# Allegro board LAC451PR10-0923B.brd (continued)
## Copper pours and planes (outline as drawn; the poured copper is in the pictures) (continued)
GND on IN4 (solid shape): 77.3,141.85 77.47,141.77 77.55,141.6 77.55,138.35 77.77,137.82 78.3,137.6 81.2,137.6 81.73,137.82 81.95,138.35 81.95,141.6 82.03,141.77 82.2,141.85 82.3,141.85 82.47,141.77 82.55,141.6 82.55,141.25 82.77,140.72 83.3,140.5 83.8,140.5 83.97,140.42 84.05,140.25 84.05,131.8 84.05,131.7 84.07,131.61 84.07,130.49 83.73,130.15 75.79,130.15 75.45,130.48 75.45,140.25 75.53,140.42 75.7,140.5 76.2,140.5 76.73,140.72 76.95,141.25 76.95,141.6 77.03,141.77 77.2,141.85
GND on IN4 (solid shape): 284.65,140.78 285.18,140.56 285.4,140.03 285.4,137.76 285.57,137.71 285.95,137.44 286.1,137 286.1,133.65 286.46,132.76 287.35,132.4 295.94,132.4 296.56,132.4 296.66,132.38 296.74,132.32 298.75,131.45 300.76,132.32 300.84,132.38 300.94,132.4 303.5,132.4 304.66,131.96 305.23,130.86 305.24,130.75 305.25,130.65 305.25,111.25 305.17,111.08 304.47,110.78 304.25,110.25 304.25,108.65 304.47,108.12 305.17,107.82 305.25,107.65 305.25,107.25 305.17,107.08 305,107 303.37,107 302.84,106.78 302.62,106.25 302.62,105.25 302.54,105.08 302.37,105 290.94,105 290.81,105.13 290.81,106.16 291.27,106.61 302.06,106.61 302.22,106.78 302.69,107.31 303.37,107.51 304.45,107.51 303.93,107.98 303.74,108.65 303.74,110.25 304.02,111.04 304.74,111.48 304.74,130.65 304.73,130.75 304.72,130.86 304.3,131.6 303.5,131.89 301.05,131.89 298.75,130.94 296.45,131.89 295.94,131.89 287.35,131.89 287.28,131.89 287.22,131.89 285.02,131.89 284,132.9 284,140.53 284.08,140.7 284.25,140.78
GND on IN4 (solid shape): outline of 122 points within 0.25,27.1 71.76,141.85
GND on IN4 (solid shape): outline of 706 points within 167.46,44.09 183.27,47.33
GND on IN4 (solid shape): outline of 158 points within 98.45,126.72 266.9,142.2
GND on IN4 (solid shape): outline of 196 points within 26.95,0.25 304.55,42.16
GND on IN4 (solid shape): outline of 1881 points within 94.37,39.68 115.32,51.68
GND on GND1: outline of 482 points within 0.26,0.26 305.25,142.19
GND on GND2: outline of 482 points within 0.26,0.26 305.25,142.19
GND on VCC: outline of 114 points within 281.91,54.17 305.25,140.77
GND on VCC: outline of 82 points within 201.57,129.07 266.9,142.19
GND on VCC: 1,27.11 0.47,27.32 0.26,27.85 0.26,60.3 0.47,60.83 1,61.05 9.19,61.05 9.12,60.97 9.12,60.76 10.39,59.49 10.39,55.17 11.93,53.63 38.47,53.63 38.83,53.27 38.83,48.27 38.35,47.79 17.9,47.79 16.36,46.24 16.36,40.7 19.93,37.12 28.54,37.12 28.47,36.94 28.44,36.75 28.44,27.35 28.37,27.18 28.2,27.11 27.2,27.11 27.03,27.18 26.95,27.35 26.95,30.65 27.02,30.68 27.12,30.74 27.2,30.82 27.27,30.92 27.31,31.02 27.34,31.13 27.36,31.25 27.35,31.36 27.32,31.47 27.27,31.58 27.2,31.67 27.12,31.75 27.03,31.82 26.92,31.87 26.81,31.9 26.7,31.91 26.58,31.89 26.47,31.86 26.37,31.82 26.27,31.75 26.19,31.67 26.13,31.57 26.1,31.51 6.3,31.51 6.27,31.57 6.21,31.67 6.13,31.75 6.03,31.82 5.93,31.86 5.82,31.89 5.7,31.91 5.59,31.9 5.48,31.87 5.37,31.82 5.28,31.75 5.2,31.67 5.13,31.58 5.08,31.47 5.05,31.36 5.04,31.25 5.06,31.13 5.09,31.02 5.13,30.92 5.2,30.82 5.28,30.74 5.38,30.68 5.44,30.65 5.44,27.35 5.37,27.18 5.2,27.11
GND on VCC: 163.04,82.61 166.99,78.66 172.64,78.66 173.22,78.08 178.3,78.08 178.75,77.63 179.76,77.63 180.08,77.32 185.94,77.32 186.83,78.21 190.77,78.21 191.34,78.78 193.54,78.78 194.18,78.14 200.66,78.14 200.82,77.98 200.82,76.06 202.18,74.71 205.1,74.71 229.21,50.6 229.21,39 227.94,37.73 227.94,37.52 227.95,37.51 166.27,37.51 166.12,37.56 165.56,38.48 164.7,38.79 164,38.79 163.14,38.48 162.59,37.56 162.43,37.51 159.8,37.51 159.63,37.58 159.56,37.75 159.56,39.2 157.1,41.65 154.65,39.2 154.65,37.75 154.57,37.58 154.4,37.51 152.4,37.51 152.23,37.58 152.16,37.75 152.16,38.75 151.93,39.28 151.4,39.51 142.4,39.51 141.87,39.28 141.65,38.75 141.65,37.75 141.57,37.58 141.4,37.51 84.03,37.51 84.05,37.52 84.05,37.73 82.78,39 82.78,58.22 100.53,75.98 109.3,75.98 123.52,90.2 148.33,90.2 148.94,89.59 148.94,86.92 150.11,85.76 155.27,85.76 156.18,86.67 156.18,87.92 162.17,87.92 163.04,87.05
GND on VCC: 73.12,72.68 73.12,77.65 75.39,79.92 76.7,79.92 76.93,79.68 76.93,75.83 73.78,72.68
GND on VCC: 53.16,54.14 52.68,54.62 52.68,56.57 52.91,56.8 55.24,56.8 55.47,56.57 55.47,54.37 55.24,54.14
GND on VCC: 58.63,127.67 56.86,129.44 56.45,129.71 55.97,129.8 55.47,129.8 55.47,129.81 51.25,129.81 50.02,130.32 49.51,131.55 49.51,139.65 49.72,140.18 50.25,140.39 51.85,140.39 52.38,140.62 52.6,141.15 52.6,141.6 52.68,141.77 52.85,141.85 59.3,141.85 59.47,141.77 59.54,141.6 59.54,141.25 59.77,140.72 60.3,140.5 60.8,140.5 60.97,140.42 61.05,140.25 61.05,131.8 61.67,131.06 62.51,131.55 73.99,131.55 74.83,131.06 75.46,131.8 75.46,140.25 75.53,140.42 75.7,140.5 76.2,140.5 76.73,140.72 76.96,141.25 76.96,141.6 77.03,141.77 77.2,141.85 77.3,141.85 77.47,141.77 77.55,141.6 77.55,138.35 77.77,137.82 78.3,137.6 81.2,137.6 81.73,137.82 81.96,138.35 81.96,141.6 82.03,141.77 82.2,141.85 82.3,141.85 82.47,141.77 82.54,141.6 82.54,141.25 82.77,140.72 83.3,140.5 83.8,140.5 83.97,140.42 84.04,140.25 84.04,138.35 84.05,131.8 84.67,131.06 85.51,131.55 96.99,131.55 97.83,131.06 98.46,131.8 98.46,140.25 98.53,140.42 98.7,140.5 100.85,140.5 101.38,140.28 101.59,139.75 101.59,134.35 102.85,130.3 106.19,127.67
GND on GND3: outline of 483 points within 0.26,0.26 305.25,142.19
GNDA on TOP (solid shape): 292.81,77.44 292.81,75.43 292.54,75.16 291.65,75.16 291.5,75.31 291.5,76.52 291.68,76.69 291.68,77.42 291.88,77.62 292.63,77.62
GNDA on TOP (solid shape): 300.06,76.75 300.06,74.46 299.84,74.25 298.92,74.25 298.34,74.82 298.34,75.39 298.07,75.66 296.56,75.66 296.08,75.19 294.49,75.19 294.43,75.26 294.43,76.6 294.8,76.98 299.83,76.98
GNDA on TOP (solid shape): 294.06,74.06 294.06,73.79 293.78,73.5 293.02,73.5 292.15,72.64 291.23,72.64 291.16,72.71 291.16,73.48 291.19,73.51 292.05,73.51 292.77,74.22 293.07,74.22 293.16,74.32 293.81,74.32
GNDA on TOP (solid shape): 295.1,67.13 295.1,66.58 295.35,66.34 295.79,66.34 295.79,66.34 296.34,66.34 296.7,65.98 296.7,65.54 296.52,65.36 296.15,65.36 295.95,65.56 295.39,65.56 295.32,65.49 294.51,65.49 294.17,65.83 294.17,66.36 294,66.52 294,67.13 294.16,67.28 294.95,67.28
GNDA on GND1, GND2, GND3: 285.45,40.17 281.91,43.7 281.91,56.95 282.27,57.31 288.24,57.31 289.15,58.22 289.15,67.24 289.26,67.34 291.29,67.34 291.69,67.75 291.69,72.28 291.29,72.68 290.53,72.68 290.29,72.91 290.29,78.41 290.53,78.65 293.87,78.65 295.52,77 300.35,77 300.71,76.64 300.71,62.12 297.81,59.22 294.89,59.22 292.96,57.29 292.96,54.92 293.11,54.77 293.29,54.77 294.14,53.92 303.89,53.92 303.89,52.17 303.82,52 303.65,51.92 292.15,51.92 291.41,51.3 291.9,50.46 291.9,45.08 291.41,44.24 292.15,43.62 303.65,43.62 303.82,43.54 303.89,43.37 303.89,41.31 297.43,41.31 296.28,40.17
GNDA on VCC: 285.45,40.17 281.91,43.7 281.91,56.95 282.27,57.31 288.24,57.31 289.15,58.22 289.15,67.24 289.26,67.34 291.29,67.34 291.69,67.75 291.69,72.28 291.29,72.68 290.53,72.68 290.29,72.91 290.29,78.41 290.53,78.65 293.87,78.65 295.52,77 300.35,77 300.71,76.64 300.71,62.12 297.81,59.22 294.89,59.22 292.96,57.29 292.96,54.92 293.11,54.77 293.29,54.77 294.14,53.92 302.88,53.92 302.88,52.94 292.15,52.94 290.52,51.86 290.88,49.94 290.88,45.6 290.52,43.68 292.15,42.6 302.88,42.6 302.88,41.31 297.43,41.31 296.28,40.17
VCCSA_B+ on TOP (solid shape): 130.21,112.37 130.21,110.97 128.94,110.97 128.75,111.16 128.75,112.18 129,112.43 130.15,112.43
VCCSA_B+ on BOTTOM (solid shape): 130.91,112.87 130.4,112.87 130.21,112.68 130.21,110.13 130.16,110.08 127.8,110.08 127.73,110.14 127.73,110.4 128.31,110.4 128.31,110.91 127.73,110.91 127.73,112.81 128.37,113.45 130.91,113.45
VDD_1.2V on BOTTOM (solid shape): 81.38,76.42 81.38,74.9 81.32,74.84 79.22,74.84 79.16,74.9 79.16,75.2 79.23,75.38 79.2,75.58 79.22,75.6 79.6,75.6 79.92,75.92 79.92,76.49 79.98,76.55 81.25,76.55
VIN_1.8VALW on TOP (solid shape): 295.81,5.43 295.81,4.9 295.29,4.9 295.27,4.89 295.27,4.35 295.82,4.35 295.82,4.1 295.29,4.1 295.27,4.09 295.27,3.55 295.82,3.55 295.82,3.07 295.62,2.87 294.74,2.87 293.77,3.83 291.67,3.83 290.85,4.64 290.85,4.94 291.02,5.1 291.7,5.1 292.21,5.61 295.63,5.61
VIN_1V_PRIM on TOP (solid shape): 245.91,94.27 245.91,90.46 246,90.37 246,89.28 246.56,89.28 246.56,89.1 246,89.1 246,88.68 245.76,88.44 245.09,88.44 244.64,88.9 244.64,90.71 243.93,91.42 242.88,91.42 242.8,91.51 242.8,92.74 244.64,94.59 245.59,94.59
VIN_1VS_VCCIO on TOP (solid shape): 239.91,42.61 239.91,41.86 239.8,41.75 239.29,41.75 238.89,41.35 237.17,41.35 236.96,41.56 236.96,42.69 237.27,43 237.27,43.91 237.37,44.01 238.5,44.01
VIN_1VS_VCCIO on BOTTOM (solid shape): 239.19,44.22 239.83,44.22 240.08,43.96 240.08,41.88 239.91,41.71 239.02,41.71 238.69,41.38 237.24,41.38 237.11,41.51 237.11,43.95 237.38,44.21 239.01,44.21 239.01,44.74 239.19,44.74
+BL_PWR_SRC on TOP (solid shape): outline of 86 points within 89.76,110.68 94.46,114.84
+BL_PWR_SRC on BOTTOM (solid shape): 95.34,111.97 95.65,111.62 96.04,111.88 96.07,111.88 96.09,111.87 96.2,111.82 96.32,111.82 96.34,111.83 97.15,111.27 97.41,111.1 97.44,111.02 97.46,110.98 96.8,110.05 96.71,110.05 96.49,110.21 95.78,110.71 94.96,110.71 94.87,110.8 93.08,110.8 92.95,110.93 92.95,111.18 93.53,112.01 95.32,112.01
+DC_IN on TOP (solid shape): 78.08,101.52 78.08,100.87 78.28,100.67 78.28,99.65 78.15,99.52 76.89,99.52 76.29,98.92 76.29,98.57 75.79,98.08 74.14,98.08 73.84,97.78 73.75,97.75 73.67,97.81 73.18,97.97 73.15,97.45 73.18,97.37 73.15,97.29 73.04,97.15 73.01,96.98 73,96.94 72.11,96.05 70.58,96.05 70.39,96.24 70.39,99.73 70.65,99.98 76.43,99.98 77.26,100.82 77.26,101.47 77.41,101.62 77.98,101.62
+DC_IN_SS on TOP (solid shape): 70.08,81.31 70.08,79.28 69.82,79.03 67.41,79.03 67.16,79.28 67.16,81.14 67.18,81.21 67.54,81.57 69.82,81.57
+DC_IN_SS on TOP (solid shape): 75.92,92.74 75.92,90.46 75.54,90.08 73.63,90.08 72.87,90.84 71.47,90.84 70.71,91.6 69.31,91.6 69.19,91.73 69.19,95.03 69.7,95.54 73.12,95.54
+DC_IN_SS on BOTTOM (solid shape): 8.81,59.91 8.91,59.85 8.88,59.74 9.12,59.11 9.35,59.74 9.32,59.85 9.42,59.91 14.41,59.91 14.74,59.58 14.74,57.25 13.22,55.72 8.48,55.72 7.66,56.55 7.66,57.03 7.66,57.04 7.69,57.18 7.66,57.33 7.66,57.34 7.66,59.47 8.1,59.91
+DC_IN_SS on VCC: 12.14,54.14 10.89,55.38 10.89,59.49 11.43,60.03 16.27,60.03 16.27,61.03 44.99,61.03 59.14,68.87 67.65,82.63 69.25,82.63 72.27,85.65 69.25,88.67 68.89,88.67 69.07,91.72 68.95,94.78 74.54,94.78 75.03,94.29 75.03,80.28 72.62,77.86 72.62,72.53 57.4,57.31 52.7,57.31 52.17,56.78 52.17,54.62 51.68,54.14
+DCIN on TOP (solid shape): 56.61,53.56 58.39,53.56 58.39,50.07 58.27,49.95 57.44,49.95 57.25,50.14 57.25,52.17 56.49,52.93 55.26,52.93 55.15,53.03 55.15,53.82 55.22,53.88 56.3,53.88
+DCIN_JACK on TOP (solid shape): 77.06,103.79 77.06,101 76.43,100.36 72.87,100.36 72.24,101 72.24,103.79 72.62,104.17 76.68,104.17
+DCIN_JACK on BOTTOM (solid shape): 75.79,104.56 76.55,102.14 76.81,101.25 76.68,100.87 73.76,100.24 73.38,100.49 72.62,103.03 72.49,103.41 72.62,103.92 75.41,104.68
+DCPRTC on BOTTOM (solid shape): 168.8,80.93 168.8,80.55 169.41,79.94 169.41,79.59 169.23,79.41 169.08,79.41 168.9,79.59 168.9,79.69 168.85,79.99 168.57,80.12 168.38,80.31 168.38,80.72 168.38,80.74 168.38,81.01 168.46,81.08 168.65,81.08
+DOCK_PWR_BAR on TOP (solid shape): 10.89,46.07 14.45,46.07 14.58,45.94 14.58,43.98 14.26,43.66 8.1,43.66 7.72,44.04 7.72,46.64 7.97,46.9 10.07,46.9
+DOCK_PWR_BAR on TOP (solid shape): outline of 217 points within 130.58,128.2 135.35,136.9
+DOCK_PWR_BAR on BOTTOM (solid shape): 173.64,136.44 173.64,129.6 174.89,128.35 174.89,126.22 174.74,126.07 172.08,126.07 171.93,126.22 171.93,136.36 172.21,136.64 173.44,136.64
+DOCK_PWR_BAR on BOTTOM (solid shape): 15.59,46.4 15.59,44.17 15.31,43.9 13.26,43.9 12.84,43.48 12.84,42.58 12.63,42.38 10.5,42.38 10.3,42.58 10.3,43.33 10.22,43.4 7.66,43.4 7.38,43.68 7.38,46.39 7.67,46.69 15.3,46.69
+DOCK_PWR_BAR on IN2 (solid shape): outline of 2764 points within 75.16,121.51 133.74,140.58
+DOCK_PWR_BAR on IN3 (solid shape): outline of 10657 points within 6.32,43.72 136.88,140.58
+DOCK_PWR_BAR on VCC: 131.01,128.69 130.66,129.04 130.66,129.98 131.93,131.25 131.93,136.2 132.28,136.56 133.47,136.56 134.11,135.92 171.65,135.92 172.29,136.56 173.48,136.56 173.58,136.45 173.58,131.99 172.95,131.35 160.37,131.35 159.36,130.34 139.95,130.34 138.3,128.69
+EDP_VDD on TOP (solid shape): 88.64,109.62 88.64,108.83 89.2,108.83 89.2,108.66 88.64,108.66 88.64,107.95 88.49,107.79 86.9,107.79 86.64,108.06 86.64,109.72 86.78,109.86 88.4,109.86
+LCDVDD on TOP (solid shape): 92.75,109.38 92.75,107.6 92.54,107.4 91.25,107.4 91.11,107.26 90.64,107.26 90.48,107.41 89.06,107.41 88.81,107.67 88.81,108.49 89.38,108.49 89.38,109 88.81,109 88.81,109.44 88.94,109.57 92.56,109.57
+LCDVDD on BOTTOM (solid shape): 92.75,108.24 92.75,106.46 93.44,105.95 93.7,105.76 93.7,105.63 93.38,105.19 93.25,105.13 92.3,105.83 92.11,105.95 92.11,106.24 92.19,106.59 91.97,106.87 91.96,106.88 91.6,107.73 91.6,108.37 91.92,108.49 92.49,108.49
+PBATT on TOP (solid shape): 76.17,55.66 76.17,49.47 76.01,49.31 75.67,49.31 75.66,49.31 73.38,49.31 73,49.69 73,55.15 73.63,55.79 76.05,55.79
+PBATT on BOTTOM (solid shape): 23.59,48.04 23.59,44.87 25.12,43.34 25.12,39.4 24.74,39.02 22.07,39.02 21.94,39.15 21.94,41.37 20.58,42.73 17.09,42.73 16.74,43.09 16.74,45.63 17.12,46.01 18.9,46.01 21.05,48.17 23.47,48.17
+PBATT on VCC: 20.14,37.63 16.86,40.91 16.86,46.03 18.11,47.28 38.98,47.28 43.05,43.21 46.69,43.21 49.1,45.63 59.01,45.63 64.97,51.6 75.56,51.6 76.17,50.98 76.17,44.84 74.01,42.68 74.01,39 73.53,38.52 59.87,38.52 57.7,39.8 55.53,38.52 37.42,38.52 37.42,39.75 34.75,42.42 32.08,39.75 32.08,38.52 29.2,38.52 28.31,38.28 27.66,37.63
+PWR_SRC on TOP (solid shape): 89.33,112.48 89.33,110.86 89.13,110.65 86.84,110.65 86.46,111.03 86.46,112.68 86.59,112.81 89,112.81
+PWR_SRC on TOP (solid shape): 98.45,120.38 98.45,116.43 97.38,115.36 94.99,115.36 94.09,116.26 94.09,120.47 95.1,121.47 97.36,121.47
+PWR_SRC on TOP (solid shape): 204.18,105.06 204.18,101.27 202.84,99.93 200.64,99.93 200.02,100.55 200.02,105.02 200.63,105.62 203.62,105.62
+PWR_SRC on TOP (solid shape): 226.1,79.16 226.65,79.16 226.65,79.71 226.9,79.71 226.9,79.18 226.91,79.18 226.91,79.16 227.56,79.16 227.68,79.03 227.68,78.01 227.49,77.82 225.21,77.82 225.08,77.95 225.08,79.03 225.21,79.16 225.85,79.16 225.85,79.71 226.1,79.71
+PWR_SRC on TOP (solid shape): 47.47,46.26 47.47,41.94 45.95,40.42 40.29,40.42 40.23,40.48 40.23,41.18 40.29,41.25 41.31,41.25 41.56,41.5 41.56,44.04 41.16,44.45 40.14,44.45 39.7,44.89 39.7,46.36 39.84,46.5 41.49,46.5 41.76,46.77 46.96,46.77
+PWR_SRC on TOP (solid shape): 67.59,64.38 67.59,63.55 68.12,63.55 68.12,63.3 67.59,63.3 67.59,62.75 68.12,62.75 68.12,62.55 68.06,62.5 67.59,62.5 67.59,62.03 67.38,61.82 66.11,61.82 65.83,62.1 65.84,62.13 65.84,62.32 65.77,62.49 65.76,62.5 65.76,62.55 65.77,62.56 65.85,62.82 65.76,63.08 65.76,64.47 66,64.72 67.26,64.72
+PWR_SRC on BOTTOM (solid shape): 232.53,93.15 232.53,91.66 231.15,90.28 229.46,90.28 228.06,91.68 228.06,94.78 228.32,95.03 230.65,95.03
+PWR_SRC on BOTTOM (solid shape): 96.7,100.16 96.7,99.2 96.68,99.18 96.14,99.18 96.14,98.45 96.16,98.42 96.68,98.42 96.68,97.98 96.15,97.98 96.14,97.96 96.14,97.23 96.68,97.23 96.68,96.3 96.37,95.98 93.18,95.98 92.54,96.62 92.54,99.73 93.44,100.63 96.23,100.63
+PWR_SRC on BOTTOM (solid shape): 54.26,134.56 54.59,134.54 54.61,134.54 54.67,134.48 54.67,134.17 54.66,134.07 54.67,133.97 54.67,131.77 54.54,131.64 53.22,131.64 53.04,131.83 53.04,133.37 53.08,133.45 53.43,133.51 53.56,133.76 53.56,134.34 53.55,134.41 53.53,134.47 53.53,134.57 53.62,134.62 53.94,134.62
+PWR_SRC on BOTTOM (solid shape): 47.34,48.17 47.34,41.31 46.45,40.42 40.29,40.42 40.23,40.48 40.23,41.18 40.29,41.25 41.18,41.25 41.56,41.63 41.56,42.83 41.18,43.21 40.91,43.21 40.83,43.25 40.81,43.34 40.49,43.74 40.16,43.34 40.14,43.25 40.06,43.21 38.83,43.21 37.4,44.65 37.4,45.87 38.79,45.87 39.14,46.22 38.79,46.58 37.4,46.58 37.4,47.11 37.95,47.66 41.83,47.66 42.21,47.53 42.47,47.84 42.47,47.86 42.49,47.88 42.49,48.45 42.73,48.7 46.81,48.7
+PWR_SRC on BOTTOM (solid shape): outline of 352 points within 209.5,75.99 234.19,80.81
+PWR_SRC on IN1 (solid shape): 62.02,128 62.78,128 63.55,127.23 63.55,127.2 64.26,126.49 64.26,123.29 63.85,122.89 61.74,122.89 61.28,123.35 61.28,126.04 60.99,126.33 60.98,126.34 60.76,126.87 60.41,127.33 57.58,130.16 57.1,130.52 56.26,130.8 55.97,130.82 53.26,130.82 53.06,131.02 53.06,133.26 53.33,133.53 56.5,133.53
+PWR_SRC on IN2 (solid shape): 64.23,125.81 64.23,123.56 63.94,123.28 62.29,123.28 62.17,123.4 62.17,125.87 62.37,126.08 63.96,126.08
+PWR_SRC on IN2 (solid shape): 87.97,112.9 87.97,111 87.64,110.67 86.78,110.67 86.47,110.98 86.47,111.54 86.25,111.77 85.42,111.77 84.76,112.43 84.76,112.87 85.99,114.1 86.76,114.1
+PWR_SRC on IN3 (solid shape): outline of 115 points within 200.6,93.41 230.96,104.59
+PWR_SRC on VCC: 43.26,43.72 39.34,47.64 39.34,53.27 39.7,53.63 55.45,53.63 55.98,54.16 55.98,56.57 56.21,56.8 57.61,56.8 72.98,72.17 73.99,72.17 77.44,75.62 77.44,79.9 76.91,80.43 76.02,80.43 75.54,80.91 75.54,102.93 89.1,116.49 96.89,116.49 97.13,116.26 97.13,115.58 88.11,106.57 88.11,101.91 89.78,100.24 93.34,100.24 93.7,99.88 93.7,96.79 92.83,95.92 84.45,95.92 82.52,93.99 82.52,69.86 58.79,46.14 48.89,46.14 46.48,43.72
+PWR_SRC_AC on TOP (solid shape): 14.64,51.6 14.64,47.02 14.45,46.83 11.08,46.83 10.51,47.41 7.97,47.41 7.59,47.79 7.59,50.07 8.23,50.71 9.89,50.71 10.83,50.71 11.12,51 11.12,51.72 11.19,51.79 14.45,51.79
+PWR_SRC_AC on BOTTOM (solid shape): 10.77,50.52 10.77,49.06 11.15,48.68 12.23,48.68 12.61,49.06 12.61,50.39 12.76,50.54 13.65,50.54 13.65,49.17 14.01,48.81 14.36,49.17 14.36,50.54 14.94,50.54 15.05,50.43 15.05,47.57 14.7,47.21 7.97,47.21 7.02,48.17 5.56,48.17 5.37,48.36 5.37,49.18 6.93,50.74 10.54,50.74
+PWR_SRC_AC on BOTTOM (solid shape): 65.25,56.1 65.25,55.6 63.73,53.44 63.24,53.25 62.46,53.77 61.81,54.22 61.8,54.23 61.48,53.78 61.12,54.04 61.43,54.48 60.83,54.91 60.82,54.91 60.61,54.62 60.5,54.47 60.14,54.73 60.45,55.18 60.3,55.28 59.82,55.61 59.81,55.68 59.78,55.87 59.98,56.17 60.46,56.84 60.5,56.81 60.97,56.91 60.91,57.39 60.87,57.42 61.57,58.39 61.95,58.39
+PWR_SRC_AC on IN2 (solid shape): outline of 2557 points within 7.47,47.02 65.12,56.42
+PWR_SRC_R on BOTTOM (solid shape): 284.78,10.68 284.78,10.04 284.55,9.81 284.55,7.91 284.5,7.85 284.16,7.85 284.07,7.95 284.07,10.07 284.16,10.17 284.16,10.66 284.26,10.77 284.7,10.77
+REGCTL_PNP10 on TOP (solid shape): 267.18,93.7 267.18,92.87 267.12,92.81 265.53,92.81 264.35,93.99 262.68,93.99 262.65,94.03 262.65,94.14 262.7,94.19 266.68,94.19
+RTC_CELL on TOP (solid shape): 245.35,74.62 245.35,74.02 245.27,73.95 244.12,73.95 243.66,73.49 243.27,73.49 243.1,73.66 243.1,74.02 243.28,74.28 243.18,74.57 243.15,74.61 243.24,74.7 245.27,74.7
+RTC_CELL on TOP (solid shape): outline of 279 points within 161.77,79.66 166.34,87.68
+SDC_IN on BOTTOM (solid shape): 14.37,55.09 14.37,54.42 14.89,53.89 14.89,51.55 14.36,51.55 14.36,52.93 14.01,53.29 13.65,52.93 13.65,51.55 11.77,51.55 11.59,51.72 9.12,51.72 8.9,51.94 8.9,54.37 9.75,55.22 14.25,55.22
+SDREG2 on TOP (solid shape): 271.12,82.6 271.12,82.18 270.77,81.83 269.99,81.83 269.92,81.9 269.92,82 270.61,82.69 271.03,82.69
+USB_LEFT_PWR on TOP (solid shape): 75.92,128.11 75.92,125.87 75.73,125.68 75.11,125.68 74.88,125.45 71.91,125.45 71.1,126.25 71.1,128.25 71.2,128.35 71.2,129.59 71.63,130.02 74.01,130.02
+USB_LEFT_PWR on BOTTOM (solid shape): 59.39,133.07 59.39,130.53 61.53,128.39 69.77,128.39 71.39,130.01 72,130.01 72.53,129.48 72.53,128.71 70.48,126.66 61.09,126.66 57.46,130.28 57.44,130.28 57.42,130.3 57.09,130.53 56.72,130.69 56.72,132.99 56.92,133.2 59.26,133.2
+USB_LEFT_PWR on IN2 (solid shape): 59.39,133.07 59.39,130.53 61.53,128.39 69.77,128.39 71.39,130.01 72,130.01 72.53,129.48 72.53,128.71 70.48,126.66 61.09,126.66 57.46,130.28 57.44,130.28 57.42,130.3 57.09,130.53 56.72,130.69 56.72,132.99 56.92,133.2 59.26,133.2
+USB_LEFT_PWR on IN3 (solid shape): 59.39,133.07 59.39,130.53 61.53,128.39 69.77,128.39 71.39,130.01 72,130.01 72.53,129.48 72.53,128.71 70.48,126.66 61.09,126.66 57.46,130.28 57.44,130.28 57.42,130.3 57.09,130.53 56.72,130.69 56.72,132.99 56.92,133.2 59.26,133.2
+USB_LEFT_PWR on IN4 (solid shape): 59.39,133.07 59.39,130.53 61.53,128.39 69.77,128.39 71.39,130.01 72,130.01 72.53,129.48 72.53,128.71 70.48,126.66 61.09,126.66 57.46,130.28 57.44,130.28 57.42,130.3 57.09,130.53 56.72,130.69 56.72,132.99 56.92,133.2 59.26,133.2
+USB_REAR_PWR on TOP (solid shape): 97.28,129.32 97.28,125.75 97.08,125.55 96.53,125.55 96.14,125.15 94.42,125.15 93.81,125.76 93.23,125.76 93.04,125.95 93.04,127.28 94.05,128.29 94.05,129.57 94.49,130.01 96.59,130.01
+USB_REAR_PWR on BOTTOM (solid shape): outline of 215 points within 78.39,124.51 95.43,130.09
+VCHGR on TOP (solid shape): 33.18,47.15 33.18,46.01 32.87,45.69 29.94,45.69 29.75,45.88 29.75,47.09 29.88,47.21 33.12,47.21
+VCHGR on BOTTOM (solid shape): 29.82,47.66 36.17,47.66 36.42,47.41 36.42,46.58 35.03,46.58 34.67,46.22 35.03,45.87 36.42,45.87 36.42,45.25 36.26,45.09 32.26,45.09 29.56,42.39 29.56,41.09 28.77,40.29 26.64,40.29 26.47,40.46 26.47,42.88 26.05,43.3 25.8,43.3 24.23,44.87 24.23,48.17 24.36,48.29 29.18,48.29
+VDISPLAY_VCC on BOTTOM (solid shape): 217.4,130.57 217.4,129.27 219.17,127.49 219.17,125.8 219.03,125.66 218.43,125.66 218.12,125.97 217.32,125.97 217.22,126.07 217.22,126.65 217.02,126.86 217.02,128.4 216.85,128.56 216.86,128.59 216.87,128.65 216.88,128.72 216.88,129.69 216.87,129.8 216.83,129.9 216.83,130.56 216.93,130.66 217.31,130.66
+VHDMI_VCC on BOTTOM (solid shape): 243.6,129.32 243.6,128.63 243.32,128.35 242.43,128.35 242.1,128.69 238.4,128.69 238.15,128.94 238.15,129.85 239.89,131.59 239.89,132.01 240.15,132.28 240.64,132.28
+VLDOIN_1.2V on BOTTOM (solid shape): 75.79,75.03 75.79,73.44 75.47,73.12 75.47,71.79 75.35,71.66 75.03,71.66 75.03,72.23 74.52,72.23 74.52,71.66 74.14,71.66 74.08,71.72 74.08,72.69 75.55,74.16 75.55,75.05 75.62,75.11 75.71,75.11
-DCIN_JACK on TOP (solid shape): outline of 106 points within 65,99.92 71.28,110.59
-DCIN_JACK on BOTTOM (solid shape): 71.8,103.15 72.3,101.38 72.17,101.13 68.43,99.79 68.17,99.92 67.84,100.85 67.59,101.68 67.32,102.5 67.36,102.64 69.94,103.56 71.39,103.56
ADJ on BOTTOM (solid shape): 223.23,105.51 223.23,104.99 222.91,104.68 222.48,104.68 221.83,104.02 220.49,104.02 220.3,104.21 219.33,104.21 219.24,104.3 219.24,104.42 219.34,104.52 220.24,104.52 220.49,104.77 221.32,104.77 221.66,105.11 221.66,105.49 221.74,105.57 223.16,105.57
AUD_HP_OUT_L1 on TOP (solid shape): 285.7,53.69 288.64,53.69 289.02,53.31 289.02,52.55 288.83,52.36 287.82,52.36 287.31,52.87 287.3,52.85 284.11,52.85 284.06,52.9 284.06,54.47 284.21,54.62 284.77,54.62
BL_PWR_SRC_ON on TOP (solid shape): 89.32,114.73 89.32,113.42 89.04,113.14 86.48,113.14 86.34,113.28 86.34,114.37 86.48,114.51 88.15,114.51 88.53,114.89 89.15,114.89
BOOT_1.2V on BOTTOM (solid shape): 76.17,75.05 76.17,73.63 76.87,72.93 77.25,72.93 77.32,72.87 77.32,72.23 77.25,72.17 76.24,72.17 75.96,72.45 75.96,75.04 76.02,75.1 76.12,75.1
BQ24770_REGN on TOP (solid shape): 53.76,53.82 53.76,51.02 53.69,50.96 52.87,50.96 52.74,50.83 51.03,50.83 50.96,50.9 50.96,51.41 51.03,51.47 52.55,51.47 53.54,52.46 53.54,53.82 53.6,53.88 53.69,53.88
BST_3V on TOP (solid shape): 220.59,88.03 220.59,86.94 220.46,86.81 219.49,86.81 219.34,86.97 219.34,88.01 219.5,88.17 220.45,88.17
BST_3V on BOTTOM (solid shape): 220.44,87.66 220.43,87.63 220.41,87.57 220.41,87.51 220.44,87.35 220.56,87.24 220.59,87.22 220.59,87 220.45,86.86 218.52,86.86 218.46,86.92 218.46,87.11 219.08,87.72 220.38,87.72
BST_5V on BOTTOM (solid shape): 212.51,87.51 212.51,86.6 212.45,86.54 211.73,86.54 211.06,87.21 210.21,87.21 210.14,87.28 210.14,87.41 210.38,87.65 212.38,87.65
BST_+1VALWP_C on BOTTOM (solid shape): 226.88,83.01 226.88,82.16 226.79,82.08 225.14,82.08 225.07,82.15 225.07,83 225.17,83.09 226.79,83.09
CHAGER_SRC on TOP (solid shape): 60.74,48.76 60.74,43.76 61.22,43.28 61.93,43.28 61.98,43.24 61.98,42.43 61.87,42.33 58.86,42.33 58.73,42.46 58.73,43.27 58.73,43.27 58.73,43.47 58.65,43.56 57.74,43.56 57.43,43.25 57.43,43.02 57.02,42.6 56.44,42.6 56.4,42.64 56.4,48.08 57.12,48.8 60.7,48.8
CHAGER_SRC on BOTTOM (solid shape): 60.23,55.13 59.94,54.68 59.97,54.66 60.54,54.27 60.65,54.43 60.84,54.71 61.25,54.42 61.06,54.15 60.93,53.98 61.52,53.57 61.63,53.75 61.82,54.01 63.25,53.04 63.41,52.61 59.34,47.02 57.69,47.02 57.19,47.53 57.19,50.74 58.53,50.74 58.53,50.72 58.54,50.67 58.56,50.62 58.58,50.57 58.61,50.53 58.65,50.49 58.69,50.46 58.74,50.44 58.79,50.42 58.84,50.41 58.89,50.41 58.94,50.42 58.99,50.44 59.04,50.46 59.08,50.49 59.11,50.53 59.15,50.57 59.17,50.62 59.19,50.67 59.19,50.72 59.19,50.77 59.19,50.82 59.17,50.87 59.15,50.92 59.11,50.96 59.08,51 59.04,51.03 58.99,51.05 58.94,51.07 58.89,51.07 58.84,51.07 58.79,51.07 58.74,51.05 58.69,51.03 58.65,51 58.61,50.96 58.58,50.92 58.56,50.87 58.54,50.82 58.53,50.77 58.53,50.74 57.19,50.74 57.19,52.67 59.56,55.61
CHG_LGATE on TOP (solid shape): 52.85,43.16 52.85,42.34 52.73,42.21 51.97,42.21 51.78,42.4 51.78,42.91 52.22,43.35 52.66,43.35
CHG_LGATE on TOP (solid shape): 53.38,53.82 53.38,52.55 52.68,51.85 52.49,51.85 52.36,51.98 52.36,52.23 53.12,52.99 53.12,53.82 53.19,53.88 53.31,53.88
CHG_LGATE on IN4 (solid shape): 52.85,43.42 52.85,42.34 52.73,42.21 51.9,42.21 51.78,42.34 51.78,43.35 52.03,43.61 52.66,43.61
CHG_LGATE on IN4 (solid shape): 53.25,52.61 53.25,52.23 53.18,52.12 53.15,52 52.87,51.72 52.87,51.09 52.61,50.83 52.36,50.83 51.92,51.28 51.92,51.72 52.93,52.74 53.12,52.74
CHG_SNUB on TOP (solid shape): 52.61,40.99 52.61,39.34 52.55,39.28 50.14,39.28 50.01,39.4 50.01,40.04 50.07,40.1 51.15,40.1 51.47,40.42 51.47,40.99 51.53,41.06 52.55,41.06
CHG_SW on TOP (solid shape): 56.06,47.37 56.06,41.75 55.47,41.16 55.47,39.53 55.22,39.28 54.2,39.28 54.07,39.4 54.07,41.18 53.36,41.9 53.36,47.37 53.43,47.45 55.98,47.45
CHG_SW on TOP (solid shape): 54.96,53.82 54.96,53.06 55.28,52.74 55.73,52.74 56.3,52.17 56.3,50.96 56.23,50.9 55.34,50.9 55.28,50.96 55.28,52.36 54.71,52.93 54.71,53.82 54.77,53.88 54.9,53.88
CHG_SW on BOTTOM (solid shape): 56.49,48.48 56.49,42.2 56.11,41.82 53.53,41.82 53.05,42.3 53.05,43.08 52.3,43.83 52.3,48.55 52.55,48.8 56.17,48.8
CHG_SW on IN1 (solid shape): 56.33,45.06 56.33,44.67 55.95,44.29 55.95,43.4 55.76,43.21 55.38,43.21 55.25,43.34 55.25,45.06 55.44,45.25 56.14,45.25
CHG_SW on IN1 (solid shape): 56.8,51.72 56.8,50.9 56.61,50.71 55.98,50.71 55.79,50.9 55.79,51.72 55.28,52.23 55.28,52.55 55.47,52.74 55.79,52.74
CHG_UGATE on TOP (solid shape): 54.58,53.82 54.58,52.87 55.15,52.29 55.15,51.91 54.96,51.72 54.84,51.72 54.65,51.91 54.65,52.1 54.33,52.42 54.33,53.82 54.39,53.88 54.52,53.88
CHG_UGATE on TOP (solid shape): 58.54,43.19 58.54,42.37 58.39,42.21 58.32,42.21 58.32,42.21 57.38,42.21 57.29,42.31 57.29,42.62 57.74,43.07 57.74,43.23 57.93,43.42 58.32,43.42
CHG_UGATE on IN4 (solid shape): 58.46,43.54 58.46,42.27 58.45,42.26 57.32,42.26 57.19,42.39 57.19,43.47 57.38,43.66 58.33,43.66
CHG_UGATE on IN4 (solid shape): 54.9,52.61 54.9,52.36 55.41,51.85 55.41,50.83 55.28,50.71 54.52,50.71 54.39,50.83 54.39,52.68 54.46,52.74 54.77,52.74
CORE_SNUB on TOP (solid shape): 108.43,106.14 108.43,105.18 108.39,105.14 106.76,105.14 106.73,105.14 106.69,105.13 105.69,105.13 105.57,105.25 105.57,106.14 105.64,106.21 108.37,106.21
CORE_SW on TOP (solid shape): 108.43,103.41 108.43,102.02 108.24,101.82 106.91,101.82 106.65,102.08 106.65,103.41 106.72,103.48 108.37,103.48
CORE_SW on BOTTOM (solid shape): 111.99,103.41 111.99,102.14 111.73,101.89 109.13,101.89 109.13,101.06 111.8,101.06 111.99,100.87 111.99,99.6 111.73,99.35 106.53,99.35 105.78,100.1 105.78,102.91 105.8,102.92 107.94,102.92 108.68,103.67 111.73,103.67
CPU_B+ on TOP (solid shape): 102.98,99.47 102.98,97.26 102.86,97.15 101.14,97.15 100.83,97.46 100.83,99.72 100.98,99.87 102.57,99.87
CPU_B+ on BOTTOM (solid shape): 127.54,112.3 127.54,110.74 128.12,110.74 128.12,110.56 127.54,110.56 127.54,109.95 127.42,109.83 126.78,109.83 126.59,110.02 126.59,112.3 126.78,112.49 127.35,112.49
CPU_B+ on BOTTOM (solid shape): 105.38,109.89 105.38,106.97 105.26,106.84 102.84,106.84 101.32,105.32 101.32,102.78 101.57,102.52 101.88,102.52 102.3,102.94 103.19,102.94 103.22,102.9 103.22,98.33 99.25,94.36 99.25,91.19 98.46,90.39 97.4,90.39 97.4,90.91 96.89,90.91 96.89,90.39 96.6,90.39 96.6,90.91 96.09,90.91 96.09,90.39 95.67,90.39 95.54,90.52 95.54,93.16 95.65,93.28 95.65,94.83 96.82,95.99 96.82,97.36 96.3,97.36 96.3,97.85 96.81,97.85 96.82,97.85 96.82,98.56 96.3,98.56 96.3,99.05 96.82,99.05 96.84,99.08 96.84,99.95 97.25,100.36 98.78,100.36 99.29,100.87 99.29,109.13 100.3,110.14 105.13,110.14
CPU_B+ on IN2 (solid shape): 101.86,99.79 101.86,98.18 101.52,97.84 99.63,97.84 99.34,98.13 99.34,99.82 99.45,99.93 101.72,99.93
CPU_B+ on IN2 (solid shape): 127.42,112.62 127.42,111.41 127.35,111.35 126.64,111.35 126.53,111.46 126.53,111.98 126.08,112.43 126.08,112.87 126.27,113.06 126.97,113.06
DH_1.2V on BOTTOM (solid shape): 76.58,75.04 76.58,74.18 77.32,73.44 77.32,73.31 77.12,73.12 76.93,73.12 76.36,73.69 76.36,75.04 76.43,75.1 76.51,75.1
DH_1.2V on IN1 (solid shape): 77.32,73.44 77.32,73.31 76.55,72.55 76.17,72.55 75.79,72.93 75.79,73.31 76.55,74.08 76.68,74.08
DH_1.2V on IN1 (solid shape): 70.84,68.17 70.84,67.36 70.69,67.2 69.05,67.2 68.93,67.32 68.93,67.79 69.12,67.98 69.89,67.98 70.2,68.3 70.71,68.3
DL_1.2V on TOP (solid shape): 77.51,67.73 77.51,67.41 77.32,67.22 75.79,67.22 75.66,67.34 75.66,67.73 75.82,67.88 77.35,67.88
DL_1.2V on BOTTOM (solid shape): 78.33,75.22 78.52,75.22 78.71,75.03 78.71,74.84 78.59,74.71 77.82,74.71 77.19,75.35 77.19,75.47 77.25,75.54 78.01,75.54
DL_1.2V on IN1 (solid shape): 77.95,68.55 77.95,67.85 77.38,67.28 76.55,67.28 76.43,67.41 76.43,68.04 77.19,68.8 77.7,68.8
DL_1.2V on IN1 (solid shape): 79.22,74.52 79.22,74.27 78.71,73.76 78.52,73.76 77.63,74.65 77.63,75.09 77.76,75.22 78.52,75.22
EN_1.8VALW on TOP (solid shape): 289.48,6.92 289.48,6.5 289.38,6.4 285.57,6.4 285.46,6.51 285.46,6.97 285.54,7.06 289.34,7.06
FB_1.8VALW on TOP (solid shape): 294.82,6.9 294.82,6.45 294.73,6.36 290.95,6.36 290.85,6.46 290.85,6.87 290.99,7.01 294.71,7.01
GPU_B+ on TOP (solid shape): 92.2,79.23 92.2,77.75 92.2,77.75 92.2,76.93 91.84,76.56 89.43,76.56 89.12,76.87 89.12,78.22 89.25,78.34 89.84,78.34 91.03,79.53 91.9,79.53
GPU_B+ on BOTTOM (solid shape): 90.45,79.75 90.87,79.75 91.14,80.01 92.25,80.01 92.34,79.92 92.34,76.36 92.05,76.07 89.26,76.07 88.89,76.44 88.89,80.14 89.02,80.27 89.32,80.27 89.32,80.28 89.92,80.28
GPU_B+ on BOTTOM (solid shape): 96.47,90.24 97.02,90.24 97.02,90.78 97.21,90.78 97.27,90.78 97.27,90.24 97.75,90.24 97.79,90.2 98.7,90.2 98.94,89.96 98.94,88.01 98.4,87.47 95.9,87.47 95.54,87.84 95.54,90.06 95.71,90.23 96.22,90.23 96.22,90.78 96.47,90.78
GPU_B+ on IN2 (solid shape): outline of 271 points within 89.23,74.22 98.97,90.08
GT_SNUB1 on TOP (solid shape): 98.6,79.78 98.6,78.1 98.41,77.91 97.39,77.91 97.22,78.08 97.22,78.65 96.92,78.95 96.23,78.95 96.09,79.09 96.09,79.78 96.18,79.87 98.51,79.87
GT_SW1 on TOP (solid shape): 101.43,79.63 101.43,77.39 101.26,77.22 100.15,77.22 99.95,77.41 99.95,79.75 100,79.8 101.26,79.8
GT_SW1 on BOTTOM (solid shape): 102.45,82.63 102.45,80.84 99.72,80.84 99.72,80.03 102.45,80.03 102.45,76.53 102.07,76.15 95.24,76.15 94.89,76.5 94.89,79.96 94.96,80.02 97.25,80.02 98,80.78 98,81.39 99.51,82.9 102.19,82.9
INT_SPK_L+ on TOP (solid shape): 281.67,40.45 281.67,39.62 281.54,39.49 277.66,39.49 277.51,39.65 277.51,40.47 277.62,40.59 281.53,40.59
INT_SPK_L+ on TOP (solid shape): 289.47,75.14 289.47,73.83 289.37,73.73 289.37,72.72 289.29,72.64 289.23,72.64 289.15,72.72 289.15,74.15 289.01,74.29 289.01,75.14 289.14,75.27 289.34,75.27
INT_SPK_L+ on IN2 (solid shape): 278.14,40.27 278.14,39.62 278.03,39.51 277.47,39.51 276.53,40.45 276.53,40.61 277.06,41.14 277.26,41.14
INT_SPK_L+ on IN2 (solid shape): 289.3,77.63 289.3,76.9 289.29,76.62 289.48,76.42 289.48,74.38 289.34,74.24 289.14,74.24 289.01,74.37 289.01,76.02 287.97,77.06 287.97,77.92 288.08,78.04 288.9,78.04
INT_SPK_L- on TOP (solid shape): 281.58,33.38 281.58,32.9 281.52,32.84 278.47,32.84 278.41,32.9 278.41,33.35 278.51,33.45 281.52,33.45
INT_SPK_L- on TOP (solid shape): 288.88,75.15 288.88,74.25 288.96,74.18 288.96,72.7 288.9,72.64 288.82,72.64 288.76,72.7 288.76,73.76 288.43,74.09 288.43,75.14 288.55,75.27 288.77,75.27
INT_SPK_L- on IN2 (solid shape): 279.8,34.32 279.8,33.3 279.44,32.93 278.5,32.93 278.43,32.99 278.43,34.18 278.7,34.45 279.68,34.45
INT_SPK_L- on IN2 (solid shape): 288.88,75.79 288.88,74.38 288.76,74.25 288.57,74.25 288.43,74.39 288.43,75.22 288.15,75.5 287.47,75.5 287.39,75.59 287.39,76.39 287.51,76.51 288.16,76.51
INT_SPK_R+ on TOP (solid shape): 281.61,32.46 281.61,31.95 281.56,31.9 278.52,31.9 278.42,32 278.42,32.39 278.52,32.5 281.57,32.5
INT_SPK_R+ on TOP (solid shape): 287.73,75.13 287.73,74.18 287.73,74.18 287.73,74.05 288.18,73.61 288.18,72.68 288.11,72.61 287.95,72.61 287.92,72.65 287.92,73.57 287.26,74.23 287.26,75.13 287.4,75.27 287.59,75.27
INT_SPK_R+ on IN2 (solid shape): 287.72,75.13 287.72,74.38 287.03,73.69 286.71,73.69 286.2,74.2 286.2,74.33 287.13,75.26 287.59,75.26
INT_SPK_R+ on IN2 (solid shape): 280.77,32.34 280.77,32.05 280.26,31.54 278.57,31.54 278.44,31.67 278.44,32.3 278.56,32.42 279.7,32.42 280.08,32.8 280.31,32.8
INT_SPK_R- on TOP (solid shape): 281.82,25.8 281.82,24.99 281.68,24.85 279.89,24.85 279.79,24.95 279.79,25.82 279.93,25.95 281.67,25.95
INT_SPK_R- on TOP (solid shape): 288.3,75.14 288.3,73.97 288.57,73.71 288.57,72.7 288.5,72.64 288.41,72.64 288.36,72.69 288.36,73.58 287.84,74.1 287.84,75.14 287.97,75.27 288.17,75.27
INT_SPK_R- on IN2 (solid shape): 281.82,26.2 281.82,24.99 281.7,24.86 280.83,24.86 280.73,24.96 280.73,26.2 280.91,26.37 281.65,26.37
INT_SPK_R- on IN2 (solid shape): 288.3,75.14 288.3,72.83 288.01,72.54 287.63,72.54 287.26,72.91 287.26,73.22 287.84,73.81 287.84,75.13 287.98,75.27 288.17,75.27
INT_SPKR_L+ on TOP (solid shape): 290.36,35.2 290.36,34.57 290.1,34.31 288.43,34.31 288.25,34.49 288.25,35.2 288.4,35.35 290.21,35.35
INT_SPKR_L+ on TOP (solid shape): 281.59,39.24 281.59,37.04 281.49,36.94 280.34,36.94 280.11,37.17 280.11,37.66 280.64,38.2 280.64,39.15 280.79,39.3 281.53,39.3
INT_SPKR_L+ on BOTTOM (solid shape): 290.38,35.06 290.38,34.25 289.71,33.57 287.49,33.57 287.26,33.8 287.26,34.16 288.27,35.17 290.27,35.17
INT_SPKR_L- on TOP (solid shape): 290.4,33.18 290.4,32.56 290.22,32.38 288.48,32.38 288.31,32.55 288.31,33.28 288.43,33.4 290.18,33.4
INT_SPKR_L- on TOP (solid shape): 281.81,35.91 281.81,33.79 281.71,33.69 280.77,33.69 280.65,33.8 280.65,34.74 280.08,35.31 280.08,35.77 280.35,36.04 281.68,36.04
INT_SPKR_L- on BOTTOM (solid shape): 290.4,33.04 290.4,32.47 290.24,32.32 287.46,32.32 287.26,32.52 287.26,32.91 287.46,33.12 290.32,33.12
INT_SPKR_R+ on TOP (solid shape): 290.45,31.71 290.45,31.02 290.28,30.86 288.48,30.86 288.26,31.07 288.26,31.68 288.44,31.86 290.29,31.86
INT_SPKR_R+ on TOP (solid shape): 281.68,31.54 281.68,29.63 281.51,29.45 280.34,29.45 280.1,29.69 280.1,30.17 280.65,30.73 280.65,31.58 280.74,31.67 281.56,31.67
INT_SPKR_R+ on BOTTOM (solid shape): 290.43,31.77 290.43,31.2 290.31,31.07 287.49,31.07 287.26,31.3 287.26,31.63 287.49,31.86 290.34,31.86
INT_SPKR_R- on TOP (solid shape): 290.37,29.37 290.37,28.72 290.19,28.55 288.48,28.55 288.33,28.7 288.33,29.38 288.5,29.56 290.18,29.56
INT_SPKR_R- on TOP (solid shape): 281.59,28.39 281.59,26.26 281.52,26.18 280.73,26.18 280.67,26.25 280.67,27.26 280.1,27.83 280.1,28.22 280.43,28.55 281.44,28.55
INT_SPKR_R- on BOTTOM (solid shape): 290.37,30.35 290.37,28.99 290.27,28.89 289.42,28.89 288.49,29.82 287.45,29.82 287.26,30.01 287.26,30.4 287.46,30.6 290.12,30.6
LX_1.8VALW on TOP (solid shape): 288.57,5.1 289.32,5.1 289.48,4.94 289.48,2.97 289.23,2.71 287.08,2.71 286.89,2.9 286.89,5.48 286.97,5.56 288.11,5.56
LX_1V_PRIM on TOP (solid shape): 237.78,95.22 237.78,94.33 238.27,93.84 238.71,93.84 238.95,93.6 238.95,92.59 239.33,92.21 240.52,92.21 240.61,92.12 240.61,91.51 240.51,91.41 236.83,91.41 236.32,91.92 236.32,95.03 236.57,95.28 237.72,95.28
LX_1VS_VCCIO on TOP (solid shape): 239.81,48.74 239.81,47.85 239.75,47.79 238.48,47.79 238.1,47.41 238.1,46.26 238.03,46.2 237.34,46.2 237.27,46.26 237.27,47.15 237.11,47.31 235.86,47.31 235.66,47.5 235.66,48.64 235.87,48.85 239.7,48.85
LX_3V on TOP (solid shape): 219.27,91.31 219.27,88.99 219.11,88.83 217.87,88.83 217.63,89.07 216.23,89.07 216.06,89.23 216.06,91.34 216.27,91.55 219.03,91.55
LX_3V on BOTTOM (solid shape): 219.38,92.96 219.38,88.18 218.33,87.13 218.33,85.04 218.39,84.99 218.39,84.17 218.32,84.1 218.19,84.1 218.12,84.18 218.12,84.99 217.97,85.14 217.97,86.78 217.68,87.07 217.68,88.78 217.29,89.17 215.16,89.17 214.62,89.71 214.62,92.8 215.09,93.28 219.07,93.28
LX_5V on TOP (solid shape): 210.91,89.55 210.91,87.29 210.64,87.01 208.5,87.01 208.21,87.3 208.21,89.59 208.64,90.02 210.44,90.02
LX_5V on BOTTOM (solid shape): 213.1,92.91 213.1,89.24 212.5,88.63 212.5,87.84 212.42,87.76 210.23,87.76 210.04,87.57 210.04,87.57 210,87.53 210,85.46 210.09,85.37 210.09,84.49 210.03,84.42 209.85,84.42 209.79,84.49 209.79,85.33 209.66,85.46 209.66,87.2 209.35,87.51 209.35,88.53 208.64,89.25 208.37,89.25 207.65,89.97 207.65,92.89 208.06,93.3 212.71,93.3
NB_PSID on BOTTOM (solid shape): 78.23,105.09 78.66,103.66 78.64,103.64 78.53,103.46 78.55,103.25 78.56,103.22 78.25,102.88 77.49,102.61 77.12,102.66 76.86,103.46 76.59,104.54 76.69,104.82 76.81,104.91 77.2,105.04 77.89,105.24
Net_6 on TOP (solid shape): 217.61,92.07 209.61,92.07 209.61,100.07 217.61,100.07
PBAT_PRES#_C on BOTTOM (solid shape): 64.57,49.63 64.59,49.52 64.24,48.89 64.04,48.88 62.46,49.99 62.46,50.35 62.73,50.72 63,50.72
PBAT_SMBCLK_C on BOTTOM (solid shape): 64.76,53.15 66.22,52.14 66.26,51.9 66,51.46 65.71,51.39 64.19,52.45 64.2,52.8 64.46,53.16
PBAT_SMBDAT_C on BOTTOM (solid shape): 63.89,51.93 65.33,50.93 65.38,50.62 65.15,50.21 64.79,50.2 63.32,51.23 63.32,51.58 63.58,51.93
PBATT+_C on TOP (solid shape): outline of 130 points within 66.9,51.22 72.11,57.12
PBATT+_C on BOTTOM (solid shape): 67.98,56.55 68.32,56.32 68.79,55.96 69.01,55.73 69,55.71 69.18,55.34 69.58,55.43 69.61,55.46 70.65,54.77 70.77,54.14 69.31,51.85 67.47,51.85 65.02,53.59 65.02,54.12 66.06,55.61 66.1,55.6 66.42,55.74 66.44,56.09 66.42,56.12 67.02,56.96 67.28,56.99
PWM1_GT on TOP (solid shape): 90.6,86.37 91.12,86.37 91.35,86.14 91.35,85.89 91.22,85.76 90.33,85.76 90.22,85.87 90.22,86.13 90.02,86.33 89.19,86.33 89.13,86.39 89.13,86.52 89.19,86.58 90.38,86.58
RING2 on TOP (solid shape): 296.28,64.79 296.28,64.57 295.38,63.67 294.49,63.67 294.35,63.81 294.35,64.27 294.52,64.44 294.98,64.44 295.53,64.98 296.08,64.98
RING2 on TOP (solid shape): 283.83,52.55 283.83,51.61 283.73,51.51 283.16,51.51 283.02,51.37 282.66,51.37 282.59,51.44 282.59,52.52 282.83,52.76 283.61,52.76
RING2 on TOP (solid shape): 292.99,69.06 293.66,69.06 293.96,68.76 293.96,68.21 293.81,68.06 293.51,68.06 292.64,68.93 291.73,68.93 291.67,68.99 291.67,69.08 291.74,69.15 292.9,69.15
RING2 on IN1 (solid shape): 284.33,52.62 284.33,51.57 284.17,51.42 282.71,51.42 282.6,51.53 282.6,52.56 282.81,52.78 284.17,52.78
RING2 on IN1 (solid shape): 294.53,68.59 294.53,66.81 296.07,65.27 296.07,62.96 295.76,62.65 294.61,62.65 294.36,62.9 294.36,64.75 293.06,66.06 293.06,68.91 293.17,69.03 294.09,69.03
RING2_R on TOP (solid shape): 285.15,52.1 285.15,51.66 285.53,51.28 287.44,51.28 287.63,51.47 288.85,51.47 289.04,51.28 289.04,50.71 288.33,50 288.33,49.37 288.8,48.9 288.8,48.77 288.64,48.61 288.09,48.61 288.03,48.55 287.88,48.55 287.68,48.75 287.68,50.38 287.44,50.61 284.22,50.61 284.06,50.77 284.06,51.48 284.08,51.5 284.08,52.51 284.15,52.57 284.68,52.57
RING2_R on IN3 (solid shape): 301.71,53.3 301.71,52.33 301.41,52.03 300.17,52.03 299.88,52.32 299.88,52.89 299.65,53.12 290.89,53.12 288.77,51 288.77,48.68 288.66,48.57 287.81,48.57 287.73,48.66 287.73,51.12 290.47,53.86 301.15,53.86
RING2_R on IN4 (solid shape): 301.71,53.3 301.71,52.33 301.41,52.03 300.17,52.03 299.88,52.32 299.88,52.89 299.65,53.12 290.89,53.12 288.78,51.01 288.78,48.7 288.64,48.56 287.82,48.56 287.72,48.66 287.72,49.45 287.73,49.46 287.73,51.25 288.06,51.58 288.07,51.59 288.2,51.67 288.29,51.8 288.29,51.81 290.33,53.86 301.15,53.86
SA_SNUB on TOP (solid shape): 133.64,117.45 133.97,117.22 134.3,117.45 134.53,117.45 135.04,116.94 135.04,114.46 134.97,114.4 134.08,114.4 133.96,114.52 133.96,116.11 133.58,116.49 132.75,116.49 132.69,116.56 132.69,117.38 132.75,117.45
SA_SW on TOP (solid shape): 132.43,116.11 132.43,114.4 131.35,113.32 130.27,113.32 130.21,113.38 130.21,114.33 131.29,115.41 131.29,116.11 131.35,116.18 132.37,116.18
SA_SW on BOTTOM (solid shape): 134.4,115.29 134.4,112.49 134.21,112.3 132.24,112.3 130.85,113.7 128.24,113.7 128.05,113.51 126.46,113.51 126.29,113.68 126.29,113.87 126.39,113.96 127.68,113.96 127.92,114.21 127.92,114.33 128.37,114.78 130.97,114.78 131.8,115.6 134.08,115.6
SLEEVE on TOP (solid shape): 283.83,47.56 283.83,46.72 283.63,46.52 282.72,46.52 282.61,46.63 282.61,47.52 282.75,47.66 283.73,47.66
SLEEVE on TOP (solid shape): 293.99,69.5 293.99,69.26 293.91,69.19 293.09,69.19 293.01,69.27 292.55,69.27 292.48,69.33 291.71,69.33 291.66,69.38 291.66,69.5 291.72,69.56 292.68,69.56 292.82,69.7 293.79,69.7
SLEEVE on TOP (solid shape): 298.83,73.55 299,73.39 299.13,73.39 299.2,73.31 300.51,72 300.51,66.22 296.81,62.52 294.2,62.52 293.45,63.28 293.45,64.42 293.51,64.49 294.01,64.49 294.1,64.39 294.09,64.38 294.09,63.71 294.38,63.42 295.49,63.42 299.1,67.03 299.1,71.81 299.1,71.81 299.1,72.08 298.41,72.77 298.41,73.48 298.48,73.55 298.72,73.55
SLEEVE on IN4 (solid shape): 284.31,47.61 284.31,46.6 284.19,46.48 282.78,46.48 282.62,46.63 282.62,47.61 282.78,47.76 284.16,47.76
SLEEVE on IN4 (solid shape): 295.69,69.32 295.69,68.95 295.55,68.81 294.73,68.81 294.35,69.19 293.06,69.19 292.96,69.29 292.96,70.15 293.03,70.22 294.8,70.22
SLEEVE on IN4 (solid shape): 298.42,66.35 298.42,65.35 298.99,64.78 298.99,62.76 298.76,62.53 297.69,62.53 297.36,62.86 297.36,64.26 297.14,64.47 297.14,66.46 297.3,66.61 298.16,66.61
SLEEVE_R on TOP (solid shape): 287.25,47.09 287.94,47.09 288.14,47.28 288.14,48.29 288.2,48.36 289.98,48.36 290.1,48.23 290.1,47.91 289.98,47.79 288.83,47.79 288.77,47.72 288.77,47.15 289.09,46.83 289.09,46.39 288.77,46.07 287.06,46.07 286.36,46.77 284.08,46.77 284.08,48.43 284.13,48.48 285.85,48.48
SLEEVE_R on IN1 (solid shape): 299.14,53.69 299.14,52.24 298.93,52.03 297.48,52.03 297.28,52.23 297.28,52.88 297.04,53.12 291.23,53.12 290.23,52.12 290.23,47.96 290.02,47.76 289.18,47.76 289.04,47.9 289.04,52.49 290.41,53.86 298.97,53.86
SLEEVE_R on IN2 (solid shape): 299.17,53.66 299.17,52.26 298.93,52.03 297.48,52.03 297.28,52.23 297.28,52.88 297.04,53.12 291.23,53.12 290.24,52.13 290.24,47.92 290.12,47.8 289.16,47.8 289.04,47.92 289.04,52.49 290.41,53.86 298.97,53.86
SNB_+1VALWP on BOTTOM (solid shape): 222.22,87.03 222.22,86.14 222.48,85.89 223.37,85.89 223.45,85.8 223.45,84.83 223.37,84.74 221.59,84.74 221.33,85 221.33,87.03 221.46,87.16 222.1,87.16
SNUB_1.2V on TOP (solid shape): 77.19,70.01 77.19,68.93 76.81,68.55 75.09,68.55 75.03,68.61 75.03,70.27 75.09,70.33 76.87,70.33
SNUB_1.8VALW on TOP (solid shape): 291.42,3.78 291.42,2.86 291.23,2.67 289.81,2.67 289.72,2.75 289.72,3.81 289.86,3.95 291.26,3.95
SNUB_1V_PRIM on TOP (solid shape): 240,95.09 240,94.4 239.94,94.33 238.48,94.33 238.48,95.22 239.88,95.22
SNUB_1VS_VCCIO on TOP (solid shape): 241.21,48.74 241.21,46.9 241.08,46.77 240.45,46.77 240.38,46.83 240.38,48.68 240.51,48.8 241.15,48.8
SW_1.2V on TOP (solid shape): 73.51,70.27 73.51,69.57 75.09,67.98 75.09,63.22 72.49,63.22 72.49,68.49 72.36,68.61 72.36,70.27 72.43,70.33 73.44,70.33
SW_1.2V on BOTTOM (solid shape): 75.92,69.12 75.92,64.26 75.57,63.92 72.24,63.92 71.85,64.3 71.85,69.12 72.11,69.38 75.66,69.38
SW_1.2V on BOTTOM (solid shape): 77,75.03 77,74.9 78.59,73.31 78.59,72.23 78.52,72.17 77.63,72.17 77.57,72.23 77.57,73.44 76.77,74.24 76.77,75.05 76.82,75.11 76.92,75.11
SW_1.2V on IN1 (solid shape): 75.54,67.47 75.54,66.71 75.09,66.26 75.09,65.69 74.9,65.5 74.58,65.5 74.52,65.57 74.52,67.47 74.65,67.6 75.41,67.6
SW_1.2V on IN1 (solid shape): 78.52,73.38 78.52,72.87 78.39,72.74 77.63,72.74 77.51,72.87 77.51,73.63 77.06,74.08 77.06,74.2 77.25,74.39 77.51,74.39
SW_+1VALWP on TOP (solid shape): 227.92,87.42 227.92,86.53 227.56,86.17 227.56,85.76 226.86,85.06 226.86,83.92 225.65,83.92 225.65,85.12 225.34,85.43 225.34,87.32 225.62,87.6 227.74,87.6
SW_+1VALWP on BOTTOM (solid shape): 227.93,87.43 227.93,84.36 227.43,83.85 225.18,83.85 224.41,83.08 224.41,82.18 224.3,82.08 221.84,82.08 221.71,82.2 221.71,83.14 221.84,83.27 223.87,83.27 224.64,84.03 224.64,87.41 224.89,87.66 227.7,87.66
N15441884 on TOP (solid shape): 50.65,58.01 50.65,56.42 51.09,55.98 52.36,55.98 52.42,55.91 52.42,55.79 52.36,55.72 50.07,55.72 49.95,55.85 49.95,58.01 50.01,58.07 50.58,58.07
N15443707 on TOP (solid shape): 54.2,53.82 54.2,52.17 54.77,51.6 54.96,51.6 54.96,50.96 54.9,50.9 54.07,50.9 53.95,51.02 53.95,53.82 54.01,53.88 54.14,53.88
N17156946 on TOP (solid shape): 70.23,98.6 70.23,96.2 70.08,96.05 69.69,96.05 68.68,97.06 68.68,98.46 68.93,98.71 70.12,98.71
N17252180 on BOTTOM (solid shape): 6.96,47.47 6.96,45.25 6.83,45.12 6.51,45.12 6.32,45.31 6.32,46.52 6.2,46.64 5.5,46.64 5.43,46.71 5.43,47.53 5.5,47.6 6.83,47.6
N19817114 on BOTTOM (solid shape): 16.65,42.54 20.33,42.54 21.42,41.45 21.42,38.9 21.16,38.64 18.35,38.64 18.17,38.82 18.17,40.33 17.83,40.67 14.07,40.67 13.82,40.93 13.82,43.34 14.01,43.53 15.66,43.53
N19957038 on BOTTOM (solid shape): 13.69,43.47 13.69,40.67 13.94,40.42 17.35,40.42 17.56,40.2 17.58,40.18 17.58,38.88 17.35,38.64 14.07,38.64 13.05,39.66 13.05,43.47 13.12,43.53 13.62,43.53
N21009123 on BOTTOM (solid shape): 81.13,77.66 81.13,76.93 81,76.81 79.03,76.81 78.71,76.49 77.25,76.49 77.19,76.55 77.19,76.68 77.25,76.74 78.27,76.74 78.71,77.19 78.71,77.5 78.9,77.69 81.09,77.69
N28712229 on TOP (solid shape): 90.97,81.14 90.97,80.63 90.82,80.48 90.39,80.48 90.25,80.34 90.25,80.18 89.85,79.78 89.12,79.78 89.04,79.86 89.04,80.76 89.2,80.91 89.72,80.91 90.26,81.45 90.67,81.45
N28712232 on TOP (solid shape): 91,80.15 91,79.68 89.89,78.57 89.12,78.57 89.05,78.64 89.05,79.56 89.16,79.67 89.94,79.67 90.37,80.11 90.37,80.21 90.52,80.35 90.8,80.35
N28712235 on TOP (solid shape): 88.61,80.7 88.61,78.69 88.53,78.61 87.74,78.61 87.62,78.73 87.62,80.68 87.75,80.81 88.5,80.81
N32114561 on TOP (solid shape): 56.3,50.2 56.3,49.56 56.23,49.5 54.07,49.5 54.01,49.56 54.01,50.2 54.07,50.26 56.23,50.26
N32497274 on BOTTOM (solid shape): 217.04,88.18 217.04,87.29 216.95,87.2 216.36,87.2 216.3,87.26 215.51,87.26 215.3,87.47 215.3,88.1 215.49,88.29 216.93,88.29
N39381354 on TOP (solid shape): 220.55,90.92 220.55,88.99 220.4,88.83 219.56,88.83 219.47,88.92 219.47,90.9 219.58,91.01 220.46,91.01
N39381542 on BOTTOM (solid shape): 208.71,88.5 208.71,87.61 208.64,87.54 208.07,87.54 207.87,87.75 207.87,88.09 207.35,88.61 206.88,88.61 206.38,89.11 206.38,89.97 206.51,90.11 207.11,90.11
N39381565 on BOTTOM (solid shape): 213.99,88.66 213.99,86.68 213.83,86.53 213.2,86.53 213.12,86.61 213.12,88.69 213.2,88.77 213.88,88.77
N48708347 on BOTTOM (solid shape): 78.59,71.47 78.59,70.84 78.52,70.77 76.36,70.77 76.3,70.84 76.3,71.47 76.36,71.54 78.52,71.54

Small or netless copper shapes (teardrops, artwork), in the pictures only: 157 on TOP, 35 on BOTTOM, 4 on GND1, 4 on GND2, 1 on VCC, 4 on GND3

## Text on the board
Ref Des/Silkscreen Bottom: 1 | M2X3 | 2 | 3 | 7 | H7 | H8 | 5 | 4 | 6 | COPYRIGHT 2015 | ALL RIGHT RESERVED | REV:A00 | PWB:CFNCD | 10 | 9 | 8 | A | DDR4 | DIMM | B | BT | WIGI | HCA | WLAN | WWAN
User.Comments: LAC451P | 2016-09-23 | 2015-09-23 | AAZ50 | Minjia
User.37: Single 45ohm | Width/space | 4 / 4.4 | Single 50ohm | 4.8 / 3.7 | 85 ohm
User.38: FIGURE | SIZE | 8.0 | 10.0 | 12.0 | 20.0 | 28.0 | 35.0 | 39.0 | 91.0 | 94.0 | 98.0 | 110.0 | 126.0 | 134.0 | 138.0 | 173.0 | 31.0 | 40.0 | 43.0 | 47.0 | 63.0 | 71.0 | 39.0x28.0 | 39.0x33.0 | 55.0x24.0 | 67.0x31.0 | 69.0x20.0 | 69.0x28.0 | 71.0x31.0 | 75.0x31.0 | 94.0x28.0 | 100.0x31.0 | 102.0x28.0 | 102.0x31.0 | 118.0x30.0 | 55.0x43.0 | DRILL CHART: TOP to BOTTOM | ALL UNITS ARE IN MILS | TOLERANCE | +3.0/-3.0 | +2.0/-2.0 | PLATED | NON-PLATED | QTY | 5889 | 81 | 5 | 62 | 27 | 10 | 9 | 1 | 3 | 2 | 4 | 7
